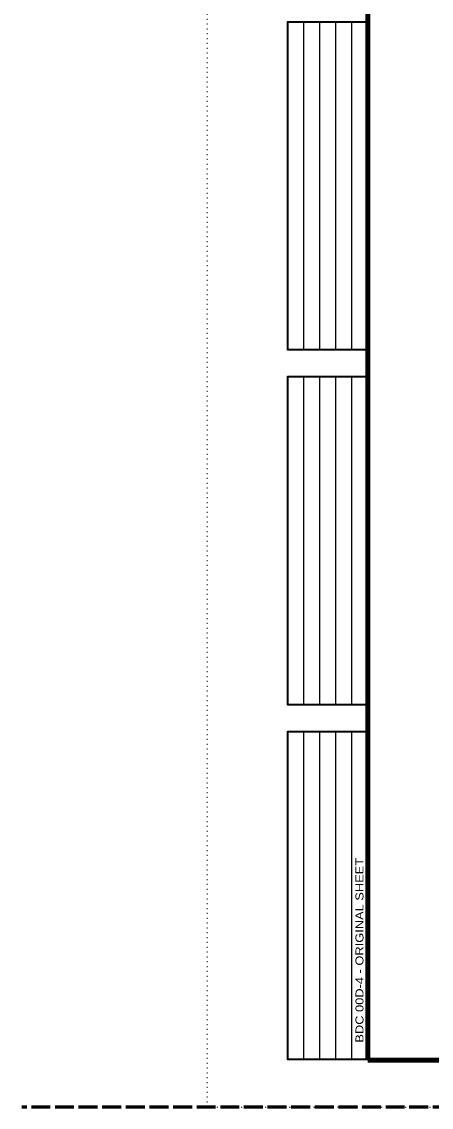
# Model space of a CAD drawing. Extents: x 312583 to 312854, y 144419 to 144597.
# Drawn here: x 312583.5 to 312622.5, y 144418.6 to 144521.9 of the extents above; entities that cross this region are included whole.
import ezdxf

# ---------------------------------------------------------------- set-up
doc = ezdxf.new("R2010")
doc.units = 0
doc.header["$LTSCALE"] = 0.3
doc.linetypes.add('DOTTED', pattern=[1.5, 0.3, -1.2])
doc.linetypes.add('LONG_DASHED', pattern=[7.5, 6, -1.5])
for name, color, linetype, lineweight in [('1', 7, 'Continuous', 25), ('62', 7, 'DOTTED', 13), ('63', 7, 'LONG_DASHED', 60)]:
    doc.layers.add(name, color=color, linetype=linetype, lineweight=lineweight)

msp = doc.modelspace()

# ---------------------------------------------------------------- linework, layer by layer
at = {"layer": '1'}
for p, q in [((312610.4087, 144490.6573), (312610.4087, 144521.8756)), ((312611.9315, 144490.6573), (312611.9315, 144521.8756)), ((312613.4543, 144490.6573), (312613.4543, 144521.8756)), ((312614.9772, 144490.6573), (312614.9772, 144521.8756)), ((312610.4087, 144456.901), (312610.4087, 144488.1192)), ((312611.9315, 144456.901), (312611.9315, 144488.1192)), ((312613.4543, 144456.901), (312613.4543, 144488.1192)), ((312614.9772, 144456.901), (312614.9772, 144488.1192)), ((312610.4087, 144423.1446), (312610.4087, 144454.3629)), ((312611.9315, 144423.1446), (312611.9315, 144454.3629)), ((312613.4543, 144423.1446), (312613.4543, 144454.3629)), ((312614.9772, 144423.1446), (312614.9772, 144454.3629))]:
    msp.add_line(p, q, dxfattribs=at)
at = {"layer": '1', "lineweight": 158}
msp.add_line((312616.5, 144423.0846), (312849, 144423.0846), dxfattribs=at)
msp.add_lwpolyline([(312616.5, 144423.1446), (312616.5, 144585.0846), (312849, 144585.0846)], dxfattribs=at)
at = {"layer": '1', "lineweight": 35}
for points in [[(312616.5, 144490.6573), (312608.8858, 144490.6573), (312608.8858, 144521.8756), (312616.5, 144521.8756)], [(312616.5, 144456.901), (312608.8858, 144456.901), (312608.8858, 144488.1192), (312616.5, 144488.1192)], [(312616.5, 144423.1446), (312608.8858, 144423.1446), (312608.8858, 144454.3629), (312616.5, 144454.3629)]]:
    msp.add_lwpolyline(points, dxfattribs=at)
at = {"layer": '62'}
msp.add_line((312601.2, 144418.5846), (312601.2, 144596.7846), dxfattribs=at)
msp.add_lwpolyline([(312601.2, 144418.5846), (312853.5, 144418.5846), (312853.5, 144596.7846)], dxfattribs=at)
at = {"layer": '63'}
msp.add_line((312851.75, 144418.5846), (312583.526, 144418.5846), dxfattribs=at)

# ---------------------------------------------------------------- texts
at = {"layer": '1', "width": 1.2}
msp.add_text('BDC 00D-4 - ORIGINAL SHEET', height=0.7614, rotation=90, dxfattribs=at).set_placement((312616.0832, 144424.7374))

doc.saveas('drawing.dxf')
